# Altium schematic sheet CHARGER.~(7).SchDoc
size A3; SheetNumber: 2; SheetTotal: 2
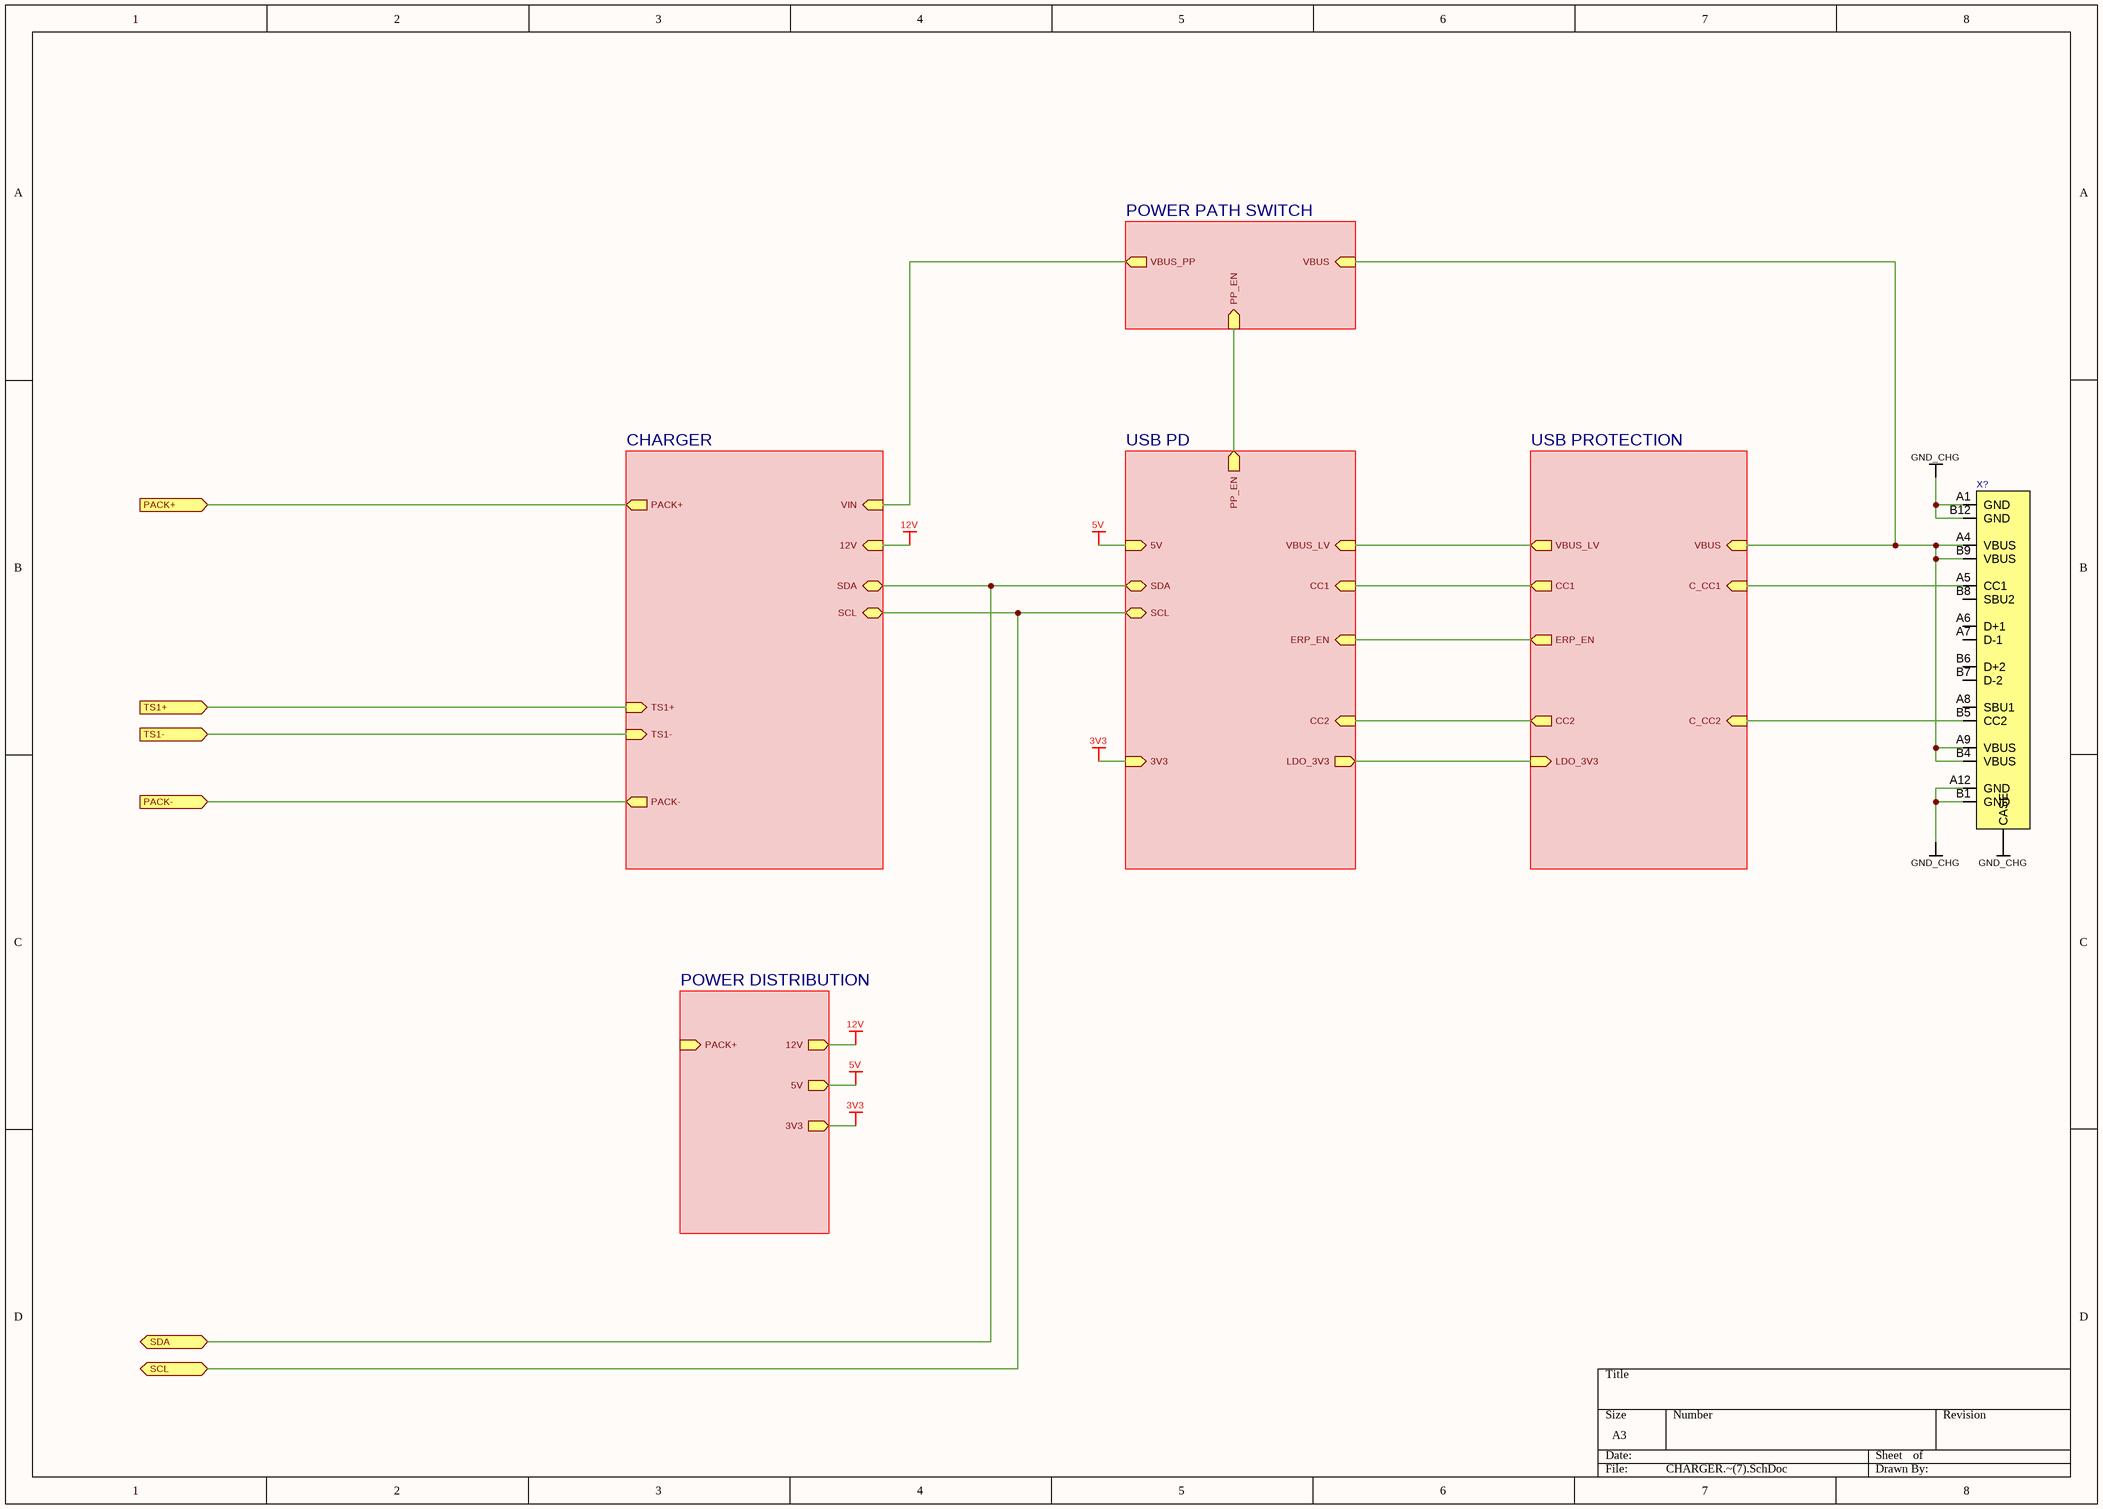
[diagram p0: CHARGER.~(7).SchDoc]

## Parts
X?  TYPE-C 16P LTH6.8  [TYPE-C 16P LTH6.8]  (value not drawn)

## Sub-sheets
CHARGER = Charger.SchDoc: PACK+ (out), VIN (in), SDA (bidir), SCL (bidir), 12V (in), PACK- (out), TS1+ (in), TS1- (in)
POWER DISTRIBUTION = Power distribution.SchDoc: PACK+ (in), 12V (out), 5V (out), 3V3 (out)
POWER PATH SWITCH = Power path switch.SchDoc: VBUS (in), VBUS_PP (out), PP_EN (in)
USB PD = USB PD.SchDoc: VBUS_LV (in), ERP_EN (in), CC1 (in), LDO_3V3 (out), SDA (bidir), SCL (bidir), 5V (in), 3V3 (in), CC2 (in), PP_EN (out)
USB PROTECTION = USB protection.SchDoc: VBUS (in), C_CC1 (in), C_CC2 (in), VBUS_LV (out), ERP_EN (out), CC1 (out), LDO_3V3 (in), CC2 (out)

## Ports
PACK+ (in, see Arhitecture[6C]), PACK- (in, see Arhitecture[6C]), SCL (bidir, see Arhitecture[6C]), SDA (bidir, see Arhitecture[6C]), TS1+ (in, see Arhitecture[6C]), TS1- (in, see Arhitecture[6C])

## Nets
3V3: sheet USB PD/3V3, sheet POWER DISTRIBUTION/3V3
5V: sheet USB PD/5V, sheet POWER DISTRIBUTION/5V
12V: sheet CHARGER/12V, sheet POWER DISTRIBUTION/12V
GND_CHG: X?.A1(GND) X?.A12(GND) X?.B1(GND) X?.B12(GND) X?.CASE
PACK+: port PACK+, sheet CHARGER/PACK+
PACK-: port PACK-, sheet CHARGER/PACK-
SCL: port SCL, sheet USB PD/SCL, sheet CHARGER/SCL
SDA: port SDA, sheet USB PD/SDA, sheet CHARGER/SDA
TS1+: port TS1+, sheet CHARGER/TS1+
TS1-: port TS1-, sheet CHARGER/TS1-
NetX?_A4: X?.A4(VBUS) X?.A9(VBUS) X?.B4(VBUS) X?.B9(VBUS) ; sheet USB PROTECTION/VBUS, sheet POWER PATH SWITCH/VBUS
NetX?_A5: X?.A5(CC1) ; sheet USB PROTECTION/C_CC1
NetX?_B5: X?.B5(CC2) ; sheet USB PROTECTION/C_CC2
(unnamed): sheet USB PROTECTION/VBUS_LV, sheet USB PD/VBUS_LV
(unnamed): sheet USB PROTECTION/ERP_EN, sheet USB PD/ERP_EN  [a separate net that carries the same name]
(unnamed): sheet USB PROTECTION/CC1, sheet USB PD/CC1  [a separate net that carries the same name]
(unnamed): sheet USB PROTECTION/LDO_3V3, sheet USB PD/LDO_3V3  [a separate net that carries the same name]
(unnamed): sheet USB PROTECTION/CC2, sheet USB PD/CC2  [a separate net that carries the same name]
(unnamed): sheet USB PD/PP_EN, sheet POWER PATH SWITCH/PP_EN  [a separate net that carries the same name]
(unnamed): sheet POWER PATH SWITCH/VBUS_PP, sheet CHARGER/VIN  [a separate net that carries the same name]

Not connected (* = marked no-connect by the designer): X? A6(D+1) A7(D-1) A8(SBU1) B6(D+2) B7(D-2) B8(SBU2)

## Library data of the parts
X? = TYPE-C 16P LTH6.8: USB-C 16P SMD Vertical 6.50mmH; Manufacturer: Shou Han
